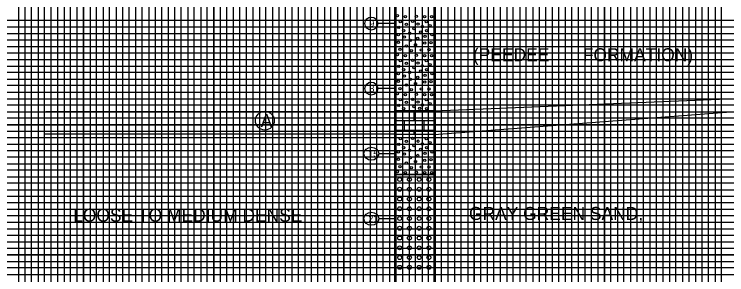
# Model space of a CAD drawing. Extents: x 2345490 to 2436403, y 465165 to 573888.
# Drawn here: x 2395666 to 2396214, y 557569 to 557769 of the extents above; entities that cross this region are included whole.
import ezdxf

# ---------------------------------------------------------------- set-up
doc = ezdxf.new("R2010")
doc.units = 0
for name, color, linetype in [('Prop Road Sect_ Boring - Material (Outline)', 7, 'Continuous'), ('Prop Road Sect_ Boring - Peripheral (SPT Oval + Leader)', 7, 'Continuous'), ('Prop Road Sect_ Boring - Peripheral (SPT Tx)', 7, 'Continuous'), ('Prop Strc Sect_ Material - Contact (General - Minor)', 7, 'Continuous'), ('Prop Strc Sect_ Material - Tx (Composite Desc)', 7, 'Continuous'), ('Sheet DOT Grid CELL', 7, 'Continuous'), ('Sheet Profile Grid Major CELL', 7, 'Continuous'), ('Sheet Profile Grid Middle CELL', 7, 'Continuous'), ('Sheet Profile Grid Minor CELL', 7, 'Continuous')]:
    doc.layers.add(name, color=color, linetype=linetype)

msp = doc.modelspace()

# ---------------------------------------------------------------- linework, layer by layer
at = {"layer": 'Prop Road Sect_ Boring - Material (Outline)'}
for p, q in [((2395958.54964, 557694.91094), (2395988.5197, 557694.91094)), ((2395958.54964, 557694.85303), (2395988.70347, 557694.85303)), ((2395973.51967, 557687.41813), (2395973.51967, 557694.91094)), ((2395988.53464, 557694.91094), (2395988.54964, 557694.91094)), ((2395958.54964, 557687.41813), (2395988.5197, 557687.41813)), ((2395966.01965, 557683.67292), (2395966.01965, 557687.41813)), ((2395966.01965, 557679.91157), (2395966.01965, 557683.65798)), ((2395981.01968, 557683.67292), (2395981.01968, 557687.41813)), ((2395981.01968, 557679.91157), (2395981.01968, 557683.65798)), ((2395988.53464, 557687.41813), (2395988.54964, 557687.41813)), ((2395958.54964, 557679.91157), (2395988.5197, 557679.91157)), ((2395958.54964, 557676.85303), (2395988.60172, 557676.85303)), ((2395973.51967, 557677.2576), (2395973.51967, 557679.91157)), ((2395988.53464, 557679.91157), (2395988.54964, 557679.91157)), ((2395988.53464, 557672.41876), (2395988.54964, 557672.41876))]:
    msp.add_line(p, q, dxfattribs=at)
for points in [[(2395958.54964, 557845.85303), (2395988.54964, 557845.85303), (2395988.54964, 557645.85303), (2395958.54964, 557645.85303)], [(2395958.54964, 557645.85303), (2395988.54964, 557645.85303), (2395988.54964, 557486.88381), (2395958.54964, 557486.88381)]]:
    msp.add_lwpolyline(points, close=True, dxfattribs=at)
for centre, radius in [((2395960.65268, 557767.95935), 0.9), ((2395962.74656, 557763.26901), 0.9), ((2395966.7727, 557767.13435), 0.9), ((2395972.19837, 557763.50087), 0.9), ((2395975.08271, 557767.40435), 0.9), ((2395981.48773, 557767.13435), 0.9), ((2395982.74269, 557763.26901), 0.9), ((2395986.79774, 557767.13435), 0.9), ((2395961.61269, 557758.9294), 0.9), ((2395967.52551, 557761.3197), 0.9), ((2395973.24767, 557757.94768), 0.9), ((2395976.43493, 557761.4258), 0.9), ((2395979.71772, 557759.3344), 0.9), ((2395985.70273, 557760.2944), 0.9), ((2395961.34269, 557753.21438), 0.9), ((2395965.42269, 557756.34939), 0.9), ((2395970.0427, 557754.44439), 0.9), ((2395978.48772, 557755.25439), 0.9), ((2395982.98773, 557756.34939), 0.9), ((2395987.06774, 557753.21438), 0.9), ((2395961.34269, 557747.36437), 0.9), ((2395965.9627, 557751.44438), 0.9), ((2395970.6127, 557748.86438), 0.9), ((2395976.25272, 557750.40938), 0.9), ((2395981.62273, 557746.80937), 0.9), ((2395981.89273, 557751.98438), 0.9), ((2395986.39274, 557747.09437), 0.9), ((2395962.55769, 557741.90436), 0.9), ((2395967.4627, 557744.63437), 0.9), ((2395974.48271, 557745.62437), 0.9), ((2395979.02772, 557741.55936), 0.9), ((2395984.75773, 557741.64936), 0.9), ((2395960.65268, 557737.97435), 0.9), ((2395966.7727, 557737.14935), 0.9), ((2395971.27271, 557740.95936), 0.9), ((2395975.08271, 557737.41935), 0.9), ((2395981.48773, 557737.14935), 0.9), ((2395986.79774, 557737.14935), 0.9), ((2395962.74656, 557733.28401), 0.9), ((2395967.52551, 557731.3347), 0.9), ((2395972.19837, 557733.51587), 0.9), ((2395976.43493, 557731.4408), 0.9), ((2395982.74269, 557733.28401), 0.9), ((2395961.61269, 557728.9444), 0.9), ((2395965.42269, 557726.36439), 0.9), ((2395973.24767, 557727.96268), 0.9), ((2395978.48772, 557725.26939), 0.9), ((2395979.71772, 557729.3494), 0.9), ((2395982.98773, 557726.36439), 0.9), ((2395985.70273, 557730.3094), 0.9), ((2395961.34269, 557723.22938), 0.9), ((2395965.9627, 557721.45938), 0.9), ((2395970.0427, 557724.45939), 0.9), ((2395976.25272, 557720.42438), 0.9), ((2395981.89273, 557721.99938), 0.9), ((2395987.06774, 557723.22938), 0.9), ((2395961.34269, 557717.37937), 0.9), ((2395967.4627, 557714.64937), 0.9), ((2395970.6127, 557718.87938), 0.9), ((2395974.48271, 557715.63937), 0.9), ((2395981.62273, 557716.82437), 0.9), ((2395986.39274, 557717.10937), 0.9), ((2395962.55769, 557711.91936), 0.9), ((2395971.27271, 557710.97436), 0.9), ((2395979.02772, 557711.57436), 0.9), ((2395984.75773, 557711.66436), 0.9), ((2395960.65268, 557707.98935), 0.9), ((2395962.74656, 557703.29901), 0.9), ((2395966.7727, 557707.16435), 0.9), ((2395972.19837, 557703.53087), 0.9), ((2395975.08271, 557707.43435), 0.9), ((2395981.48773, 557707.16435), 0.9), ((2395982.74269, 557703.29901), 0.9), ((2395986.79774, 557707.16435), 0.9), ((2395961.61269, 557698.9594), 0.9), ((2395967.52551, 557701.3497), 0.9), ((2395973.24767, 557697.97768), 0.9), ((2395976.43493, 557701.4558), 0.9), ((2395979.71772, 557699.3644), 0.9), ((2395985.70273, 557700.3244), 0.9), ((2395965.42269, 557696.37939), 0.9), ((2395977.74156, 557696.77672), 0.9), ((2395982.98773, 557696.37939), 0.9), ((2395962.74656, 557673.31401), 0.9), ((2395967.52551, 557671.3647), 0.9), ((2395972.19837, 557673.54587), 0.9), ((2395976.43493, 557671.4708), 0.9), ((2395982.74269, 557673.31401), 0.9), ((2395985.70273, 557670.3394), 0.9), ((2395961.61269, 557668.9744), 0.9), ((2395965.42269, 557666.39439), 0.9), ((2395973.24767, 557667.99268), 0.9), ((2395978.48772, 557665.29939), 0.9), ((2395979.71772, 557669.3794), 0.9), ((2395982.98773, 557666.39439), 0.9), ((2395961.34269, 557663.25938), 0.9), ((2395965.9627, 557661.48938), 0.9), ((2395970.0427, 557664.48939), 0.9), ((2395976.25272, 557660.45438), 0.9), ((2395981.89273, 557662.02938), 0.9), ((2395987.06774, 557663.25938), 0.9), ((2395961.34269, 557657.40937), 0.9), ((2395967.4627, 557654.67937), 0.9), ((2395970.6127, 557658.90938), 0.9), ((2395974.48271, 557655.66937), 0.9), ((2395981.62273, 557656.85437), 0.9), ((2395986.39274, 557657.13937), 0.9), ((2395962.55769, 557651.94936), 0.9), ((2395971.27271, 557651.00436), 0.9), ((2395979.02772, 557651.60436), 0.9), ((2395984.75773, 557651.69436), 0.9), ((2395960.65268, 557648.01935), 0.9), ((2395966.7727, 557647.19435), 0.9), ((2395975.08271, 557647.46435), 0.9), ((2395981.48773, 557647.19435), 0.9), ((2395986.79774, 557647.19435), 0.9), ((2395962.28653, 557642.0197), 1.5), ((2395969.78653, 557642.0197), 1.5), ((2395977.28653, 557642.0197), 1.5), ((2395984.78653, 557642.0197), 1.5), ((2395962.28653, 557634.5197), 1.5), ((2395969.78653, 557634.5197), 1.5), ((2395977.28653, 557634.5197), 1.5), ((2395984.78653, 557634.5197), 1.5), ((2395962.28653, 557627.0197), 1.5), ((2395969.78653, 557627.0197), 1.5), ((2395977.28653, 557627.0197), 1.5), ((2395984.78653, 557627.0197), 1.5), ((2395962.28653, 557619.5197), 1.5), ((2395969.78653, 557619.5197), 1.5), ((2395977.28653, 557619.5197), 1.5), ((2395984.78653, 557619.5197), 1.5), ((2395962.28653, 557612.0347), 1.5), ((2395969.78653, 557612.0347), 1.5), ((2395977.28653, 557612.0347), 1.5), ((2395984.78653, 557612.0347), 1.5), ((2395962.28653, 557604.5347), 1.5), ((2395969.78653, 557604.5347), 1.5), ((2395977.28653, 557604.5347), 1.5), ((2395984.78653, 557604.5347), 1.5), ((2395962.28653, 557597.0347), 1.5), ((2395969.78653, 557597.0347), 1.5), ((2395977.28653, 557597.0347), 1.5), ((2395984.78653, 557597.0347), 1.5), ((2395962.28653, 557589.5347), 1.5), ((2395969.78653, 557589.5347), 1.5), ((2395977.28653, 557589.5347), 1.5), ((2395984.78653, 557589.5347), 1.5), ((2395962.28653, 557582.0497), 1.5), ((2395969.78653, 557582.0497), 1.5), ((2395977.28653, 557582.0497), 1.5), ((2395984.78653, 557582.0497), 1.5), ((2395962.28653, 557574.5497), 1.5), ((2395969.78653, 557574.5497), 1.5), ((2395977.28653, 557574.5497), 1.5), ((2395984.78653, 557574.5497), 1.5)]:
    msp.add_circle(centre, radius, dxfattribs=at)
at = {"layer": 'Prop Road Sect_ Boring - Peripheral (SPT Oval + Leader)'}
for p, q in [((2395958.54964, 557761.85303), (2395945.46696, 557761.85303)), ((2395958.54964, 557711.85303), (2395945.46696, 557711.85303)), ((2395958.54964, 557661.85303), (2395946.29373, 557661.85303)), ((2395958.54964, 557611.85303), (2395946.29373, 557611.85303))]:
    msp.add_line(p, q, dxfattribs=at)
for centre, major_axis, ratio in [((2395940.54964, 557761.85303), (0, 5), 0.983464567), ((2395940.54964, 557711.85303), (0, 5), 0.983464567), ((2395940.54964, 557661.85303), (5.74409, 0), 0.870459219), ((2395940.54964, 557611.85303), (5.74409, 0), 0.870459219)]:
    msp.add_ellipse(centre, major_axis=major_axis, ratio=ratio, dxfattribs=at)
at = {"layer": 'Prop Strc Sect_ Material - Contact (General - Minor)'}
for p, q in [((2395988.70347, 557694.85303), (2396257.06942, 557705.75521)), ((2395959.17952, 557694.11878), (2395690.59222, 557694.11878)), ((2396256.54964, 557696.83938), (2395988.74437, 557676.3582)), ((2395958.54964, 557676.85303), (2395689.96234, 557676.85303))]:
    msp.add_line(p, q, dxfattribs=at)
at = {"layer": 'Prop Strc Sect_ Material - Tx (Composite Desc)'}
msp.add_circle((2395858.77636, 557687.23994), 7.21151, dxfattribs=at)
at = {"layer": 'Sheet DOT Grid CELL'}
for p, q in [((2395669.54994, 558259.113), (2395669.54994, 557234.113)), ((2395719.54994, 558259.113), (2395719.54994, 557234.113)), ((2395769.54994, 558259.113), (2395769.54994, 557234.113)), ((2395819.54994, 558259.113), (2395819.54994, 557234.113)), ((2395869.54994, 558259.113), (2395869.54994, 557234.113)), ((2395919.54994, 558259.113), (2395919.54994, 557234.113)), ((2395969.54994, 558259.113), (2395969.54994, 557234.113)), ((2396019.54994, 558259.113), (2396019.54994, 557234.113)), ((2396069.54994, 558259.113), (2396069.54994, 557234.113)), ((2396119.54994, 558259.113), (2396119.54994, 557234.113)), ((2396169.54994, 558259.113), (2396169.54994, 557234.113)), ((2395319.54994, 557734.113), (2396819.54994, 557734.113)), ((2395319.54994, 557684.113), (2396819.54994, 557684.113)), ((2395319.54994, 557634.113), (2396819.54994, 557634.113)), ((2395319.54994, 557584.113), (2396819.54994, 557584.113))]:
    msp.add_line(p, q, dxfattribs=at)
at = {"layer": 'Sheet Profile Grid Major CELL'}
for points in [[(2395669.54994, 558259.113), (2395669.54994, 557234.113), (2395719.54994, 557234.113), (2395719.54994, 558259.113)], [(2395769.54994, 558259.113), (2395769.54994, 557234.113), (2395819.54994, 557234.113), (2395819.54994, 558259.113)], [(2395869.54994, 558259.113), (2395869.54994, 557234.113), (2395919.54994, 557234.113), (2395919.54994, 558259.113)], [(2395969.54994, 558259.113), (2395969.54994, 557234.113), (2396019.54994, 557234.113), (2396019.54994, 558259.113)], [(2396069.54994, 558259.113), (2396069.54994, 557234.113), (2396119.54994, 557234.113), (2396119.54994, 558259.113)], [(2396169.54994, 558259.113), (2396169.54994, 557234.113), (2396219.54994, 557234.113)], [(2396819.54994, 557684.113), (2395319.54994, 557684.113), (2395319.54994, 557734.113), (2396819.54994, 557734.113)], [(2396819.54994, 557584.113), (2395319.54994, 557584.113), (2395319.54994, 557634.113), (2396819.54994, 557634.113)]]:
    msp.add_lwpolyline(points, dxfattribs=at)
at = {"layer": 'Sheet Profile Grid Middle CELL'}
for points in [[(2395644.54994, 558259.113), (2395644.54994, 557234.113), (2395694.54994, 557234.113), (2395694.54994, 558259.113)], [(2395744.54994, 558259.113), (2395744.54994, 557234.113), (2395794.54994, 557234.113), (2395794.54994, 558259.113)], [(2395844.54994, 558259.113), (2395844.54994, 557234.113), (2395894.54994, 557234.113), (2395894.54994, 558259.113)], [(2395944.54994, 558259.113), (2395944.54994, 557234.113), (2395994.54994, 557234.113), (2395994.54994, 558259.113)], [(2396044.54994, 558259.113), (2396044.54994, 557234.113), (2396094.54994, 557234.113), (2396094.54994, 558259.113)], [(2396144.54994, 558259.113), (2396144.54994, 557234.113), (2396194.54994, 557234.113), (2396194.54994, 558259.113)], [(2396819.54994, 557759.113), (2395319.54994, 557759.113), (2395319.54994, 557709.113), (2396819.54994, 557709.113)], [(2396819.54994, 557659.113), (2395319.54994, 557659.113), (2395319.54994, 557609.113), (2396819.54994, 557609.113)]]:
    msp.add_lwpolyline(points, dxfattribs=at)
at = {"layer": 'Sheet Profile Grid Minor CELL'}
for points in [[(2395674.54994, 558259.113), (2395674.54994, 557234.113), (2395679.54994, 557234.113), (2395679.54994, 558259.113)], [(2395684.54994, 558259.113), (2395684.54994, 557234.113), (2395689.54994, 557234.113), (2395689.54994, 558259.113)], [(2395699.54994, 558259.113), (2395699.54994, 557234.113), (2395714.54994, 557234.113), (2395714.54994, 558259.113)], [(2395704.54994, 558259.113), (2395704.54994, 557234.113), (2395709.54994, 557234.113), (2395709.54994, 558259.113)], [(2395704.54994, 558258.513), (2395704.54994, 557234.113), (2395709.54994, 557234.113), (2395709.54994, 558258.513)], [(2395724.54994, 558259.113), (2395724.54994, 557234.113), (2395729.54994, 557234.113), (2395729.54994, 558259.113)], [(2395734.54994, 558259.113), (2395734.54994, 557234.113), (2395739.54994, 557234.113), (2395739.54994, 558259.113)], [(2395749.54994, 558259.113), (2395749.54994, 557234.113), (2395754.54994, 557234.113), (2395754.54994, 558259.113)], [(2395759.54994, 558259.113), (2395759.54994, 557234.113), (2395764.54994, 557234.113), (2395764.54994, 558259.113)], [(2395774.54994, 558259.113), (2395774.54994, 557234.113), (2395779.54994, 557234.113), (2395779.54994, 558259.113)], [(2395784.54994, 558259.113), (2395784.54994, 557234.113), (2395789.54994, 557234.113), (2395789.54994, 558259.113)], [(2395799.54994, 558259.113), (2395799.54994, 557234.113), (2395804.54994, 557234.113), (2395804.54994, 558259.113)], [(2395809.54994, 558259.113), (2395809.54994, 557234.113), (2395814.54994, 557234.113), (2395814.54994, 558259.113)], [(2395824.54994, 558259.113), (2395824.54994, 557234.113), (2395829.54994, 557234.113), (2395829.54994, 558259.113)], [(2395834.54994, 558259.113), (2395834.54994, 557234.113), (2395839.54994, 557234.113), (2395839.54994, 558259.113)], [(2395849.54994, 558259.113), (2395849.54994, 557234.113)], [(2395854.54994, 558259.113), (2395854.54994, 557234.113), (2395859.54994, 557234.113), (2395859.54994, 558259.113), (2395864.54994, 558259.113), (2395864.54994, 557234.113), (2395874.54994, 557234.113), (2395874.54994, 558259.113), (2395879.54994, 558259.113), (2395879.54994, 557234.113), (2395884.54994, 557234.113), (2395884.54994, 558259.113), (2395889.54994, 558259.113), (2395889.54994, 557234.113)], [(2395899.54994, 557234.113), (2395899.54994, 558259.113)], [(2395904.54994, 558259.113), (2395904.54994, 557234.113), (2395909.54994, 557234.113), (2395909.54994, 558259.113)], [(2395914.54994, 558259.113), (2395914.54994, 557234.113), (2395924.54994, 557234.113), (2395924.54994, 558259.113)], [(2395929.54994, 558259.113), (2395929.54994, 557234.113), (2395929.54994, 557234.113), (2395934.54994, 557234.113), (2395934.54994, 558259.113)], [(2395939.54994, 558259.113), (2395939.54994, 557234.113), (2395949.54994, 557234.113), (2395949.54994, 558259.113)], [(2395954.54994, 558259.113), (2395954.54994, 557234.113), (2395959.54994, 557234.113), (2395959.54994, 558259.113)], [(2395964.54994, 558259.113), (2395964.54994, 557234.113), (2395974.54994, 557234.113), (2395974.54994, 558259.113)], [(2395979.54994, 558259.113), (2395979.54994, 557234.113), (2395984.54994, 557234.113), (2395984.54994, 558259.113)], [(2395989.54994, 558259.113), (2395989.54994, 557234.113), (2395999.54994, 557234.113), (2395999.54994, 558259.113)], [(2396004.54994, 558259.113), (2396004.54994, 557234.113), (2396009.54994, 557234.113), (2396009.54994, 558259.113)], [(2396014.54994, 558259.113), (2396014.54994, 557234.113), (2396024.54994, 557234.113), (2396024.54994, 558259.113)], [(2396029.54994, 558259.113), (2396029.54994, 557234.113), (2396034.54994, 557234.113), (2396034.54994, 558259.113)], [(2396039.54994, 558259.113), (2396039.54994, 557234.113), (2396049.54994, 557234.113), (2396049.54994, 558259.113)], [(2396054.54994, 558259.113), (2396054.54994, 557234.113), (2396059.54994, 557234.113), (2396059.54994, 558259.113)], [(2396064.54994, 558259.113), (2396064.54994, 557234.113), (2396074.54994, 557234.113), (2396074.54994, 558259.113)], [(2396079.54994, 558259.113), (2396079.54994, 557234.113)], [(2396079.54994, 557234.113), (2396084.54994, 557234.113), (2396084.54994, 558258.513)], [(2396089.54994, 558258.513), (2396089.54994, 557234.113), (2396099.54994, 557234.113), (2396099.54994, 558259.113)], [(2396104.54994, 558259.113), (2396104.54994, 557234.113), (2396109.54994, 557234.113), (2396109.54994, 558259.113)], [(2396114.54994, 558259.113), (2396114.54994, 557234.113), (2396124.54994, 557234.113), (2396124.54994, 558259.113)], [(2396129.54994, 558259.113), (2396129.54994, 557234.113), (2396134.54994, 557234.113), (2396134.54994, 558259.113)], [(2396139.54994, 558259.113), (2396139.54994, 557234.113), (2396149.54994, 557234.113), (2396149.54994, 558259.113)], [(2396154.54994, 558259.113), (2396154.54994, 557234.113), (2396159.54994, 557234.113), (2396159.54994, 558259.113)], [(2396164.54994, 558259.113), (2396164.54994, 557234.113), (2396174.54994, 557234.113), (2396174.54994, 558259.113)], [(2396179.54994, 558259.113), (2396179.54994, 557234.113), (2396184.54994, 557234.113), (2396184.54994, 558259.113)], [(2396189.54994, 558259.113), (2396189.54994, 557234.113), (2396199.54994, 557234.113), (2396199.54994, 558259.113)], [(2396204.54994, 558259.113), (2396204.54994, 557234.113), (2396209.54994, 557234.113), (2396209.54994, 558259.113)], [(2396769.54994, 557764.113), (2395369.54994, 557764.113), (2395369.54994, 557754.113), (2396769.54994, 557754.113)], [(2396769.54994, 557749.113), (2395369.54994, 557749.113), (2395369.54994, 557744.113), (2396769.54994, 557744.113)], [(2396769.54994, 557739.113), (2395369.54994, 557739.113)], [(2395369.54994, 557729.113), (2396769.54994, 557729.113)], [(2396769.54994, 557724.113), (2395369.54994, 557724.113), (2395369.54994, 557719.113), (2396769.54994, 557719.113)], [(2396769.54994, 557714.113), (2395369.54994, 557714.113), (2395369.54994, 557704.113), (2396769.54994, 557704.113)], [(2396769.54994, 557699.113), (2395369.54994, 557699.113), (2395369.54994, 557694.113), (2396769.54994, 557694.113)], [(2396769.54994, 557689.113), (2395369.54994, 557689.113), (2395369.54994, 557679.113), (2396769.54994, 557679.113)], [(2396769.54994, 557674.113), (2395369.54994, 557674.113), (2395369.54994, 557669.113), (2396769.54994, 557669.113)], [(2396769.54994, 557664.113), (2395369.54994, 557664.113), (2395369.54994, 557654.113), (2396769.54994, 557654.113)], [(2396769.54994, 557649.113), (2395369.54994, 557649.113), (2395369.54994, 557644.113), (2396769.54994, 557644.113)], [(2396769.54994, 557639.113), (2395369.54994, 557639.113), (2395369.54994, 557629.113), (2396769.54994, 557629.113)], [(2396769.54994, 557624.113), (2395369.54994, 557624.113), (2395369.54994, 557619.113), (2396769.54994, 557619.113)], [(2396769.54994, 557614.113), (2395369.54994, 557614.113), (2395369.54994, 557604.113), (2396769.54994, 557604.113)], [(2396769.54994, 557599.113), (2395369.54994, 557599.113), (2395369.54994, 557594.113), (2396769.54994, 557594.113)], [(2396769.54994, 557589.113), (2395369.54994, 557589.113), (2395369.54994, 557579.113), (2396769.54994, 557579.113)], [(2396769.54994, 557574.113), (2395369.54994, 557574.113), (2395369.54994, 557569.113), (2396769.54994, 557569.113)]]:
    msp.add_lwpolyline(points, dxfattribs=at)

# ---------------------------------------------------------------- texts
at = {"layer": 'Prop Road Sect_ Boring - Peripheral (SPT Tx)'}
for s, p in [('9', (2395939.13232, 557759.35303)), ('8', (2395939.13232, 557709.35303)), ('15', (2395938.30555, 557659.35303)), ('21', (2395938.30555, 557609.35303))]:
    msp.add_text(s, height=5, dxfattribs=at).set_placement(p)
at = {"layer": 'Prop Strc Sect_ Material - Tx (Composite Desc)'}
for s, p in [('(PEEDEE', (2396018.55866, 557732.89288)), ('FORMATION)', (2396102.99581, 557732.8702)), ('A', (2395855.54802, 557682.23994)), ('LOOSE TO MEDIUM DENSE', (2395711.54201, 557609.6236)), ('GRAY GREEN SAND,', (2396015.5514, 557610.91137))]:
    msp.add_text(s, height=10, dxfattribs=at).set_placement(p)

doc.saveas('drawing.dxf')
